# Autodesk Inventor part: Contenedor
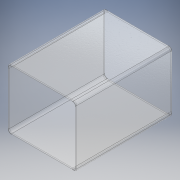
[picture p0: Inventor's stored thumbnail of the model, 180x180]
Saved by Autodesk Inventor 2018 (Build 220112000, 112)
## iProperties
Created: 2022-01
Part Number: Contenedor
Material: Plástico, transparente
Document SubType Name: Modeling
Designer: Asus
Density: 1.188 g/cm^3
Appearance: Transparente - Claro
Author: Asus
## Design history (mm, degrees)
sketch "Boceto1"
  geometry: L1 (125, 110)-(-125, 110); L2 (-125, 110)-(-125, -110); L3 (-125, -110)-(125, -110); L4 (125, -110)-(125, 110); L5 (125, 110)-(-125, -110); L6 (-125, 110)-(125, -110); L7 (-120, 105)-(120, 105); L8 (120, 105)-(120, -105); L9 (120, -105)-(-120, -105); L10 (-120, -105)-(-120, 105); L11 (-120, 105)-(120, -105); L12 (120, 105)-(-120, -105); 1 further point
  constraints: 24 end point, 4 midpoint, 4 parallel, 2 horizontal, 2 perpendicular
  dimensions: "d0" = 250 distance of L3.end L2.end; "d1" = 220 distance of L2.end L1.end; "d2" = 240 distance of L8.end L9.end; "d3" = 210 distance of L7.end L8.end
extrude "Extrusión1" new body sketch "Boceto1" distance "d4" = 350; taper "d5" = 0 deg
fillet "Empalme2" dims "d7" = 10
fillet "Empalme3" dims "d8" = 10
fillet "Empalme4" dims "d9" = 2.5
node "Sólido1"
